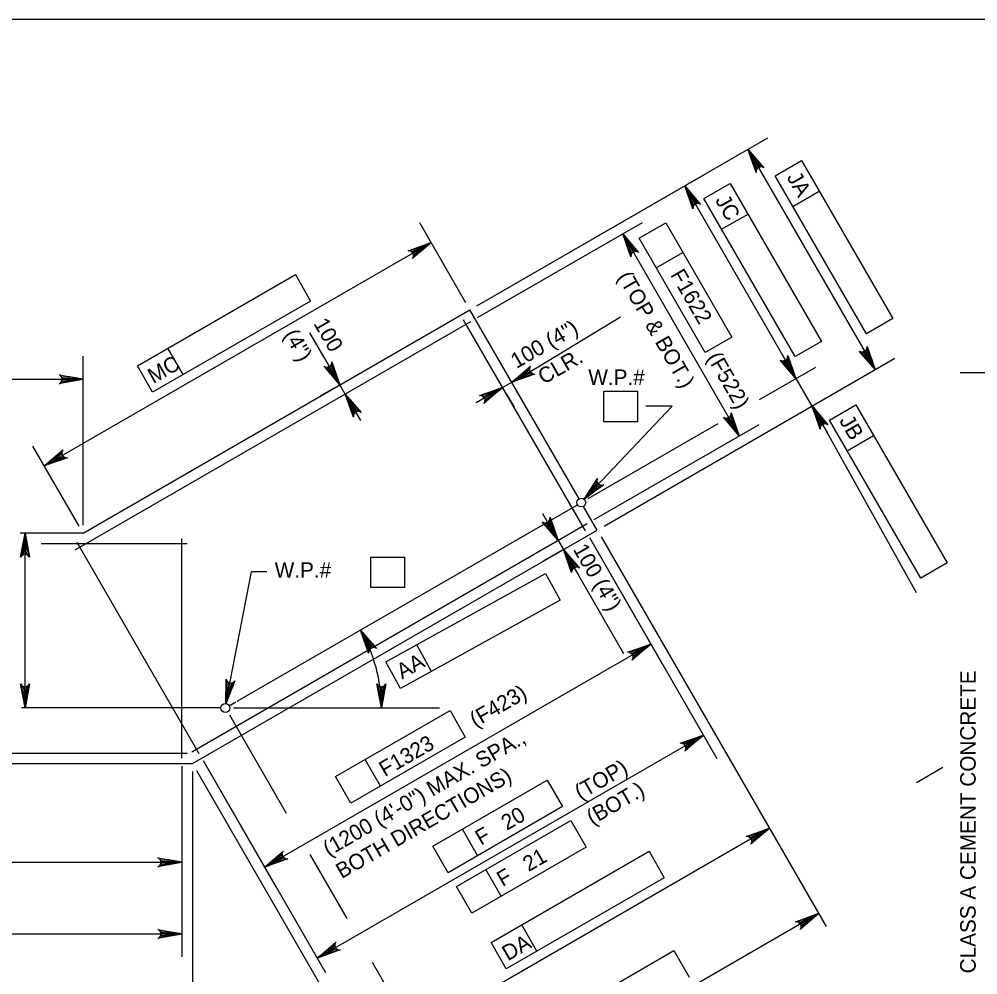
# Model space of a CAD drawing. Extents: x 634540 to 640306, y 296059 to 300275.
# Drawn here: x 639655.1 to 639840.5, y 297641.6 to 297826.5 of the extents above; entities that cross this region are included whole.
import ezdxf

# ---------------------------------------------------------------- set-up
doc = ezdxf.new("R2010")
doc.units = 0
for name, color, linetype in [('10', 7, 'Continuous'), ('2', 7, 'Continuous'), ('4', 7, 'Continuous'), ('6', 7, 'Continuous')]:
    doc.layers.add(name, color=color, linetype=linetype)

msp = doc.modelspace()

# ---------------------------------------------------------------- linework, layer by layer
at = {"layer": '10'}
for p, q in [((639667.47, 297727.03), (639742.3, 297770.24)), ((639763.41, 297733.68), (639742.3, 297770.24)), ((639697.24, 297694.5), (639763.1, 297732.52)), ((639766.91, 297727.62), (639764.26, 297732.21)), ((639688.64, 297682.43), (639766.91, 297727.62)), ((639667.47, 297727.03), (639655.32, 297727.03)), ((639695.72, 297693.62), (639697.01, 297694.37)), ((639694.14, 297693.2), (639655.55, 297693.2)), ((639468.96, 297682.43), (639688.64, 297682.43))]:
    msp.add_line(p, q, dxfattribs=at)
at = {"layer": '2'}
msp.add_line((639316.46, 297826.46), (640102.46, 297826.46), dxfattribs=at)
at = {"layer": '4'}
for p, q in [((639743.63, 297771.01), (639799.91, 297803.5)), ((639796.07, 297801.28), (639820.68, 297758.66)), ((639801.32, 297796.15), (639806.44, 297799.1)), ((639806.44, 297799.1), (639824.09, 297768.53)), ((639743.63, 297771.01), (639787.66, 297796.43)), ((639787.54, 297791.74), (639792.66, 297794.69)), ((639792.66, 297794.69), (639810.31, 297764.12)), ((639818.98, 297765.57), (639801.32, 297796.15)), ((639783.83, 297794.21), (639803.88, 297759.48)), ((639804.75, 297790.22), (639809.86, 297793.17)), ((639805.19, 297761.17), (639787.54, 297791.74)), ((639790.97, 297785.81), (639796.08, 297788.76)), ((639741.53, 297771.57), (639732.59, 297787.06)), ((639743.77, 297768.72), (639775.68, 297787.14)), ((639775.05, 297784.08), (639780.16, 297787.03)), ((639780.16, 297787.03), (639792.93, 297764.92)), ((639659.97, 297740.02), (639734.8, 297783.23)), ((639771.84, 297784.93), (639794.39, 297745.85)), ((639787.82, 297761.96), (639775.05, 297784.08)), ((639778.34, 297778.37), (639783.46, 297781.33)), ((639677.96, 297759.39), (639708.53, 297777.04)), ((639708.53, 297777.04), (639711.48, 297771.93)), ((639711.48, 297771.93), (639680.91, 297754.28)), ((639755.5, 297759.18), (639771.39, 297768.88)), ((639824.09, 297768.53), (639818.98, 297765.57)), ((639714.2, 297760.83), (639711.34, 297765.8)), ((639792.93, 297764.92), (639787.82, 297761.96)), ((639686.84, 297757.7), (639683.89, 297762.82)), ((639810.31, 297764.12), (639805.19, 297761.17)), ((639667.47, 297728.57), (639667.47, 297761.24)), ((639805.36, 297756.92), (639802.41, 297762.03)), ((639680.91, 297754.28), (639677.96, 297759.39)), ((639717.16, 297755.72), (639714.2, 297760.83)), ((639750.39, 297756.23), (639755.5, 297759.18)), ((639768.24, 297728.39), (639824.51, 297760.88)), ((639798.31, 297752.85), (639809.2, 297759.13)), ((639860.36, 297758.02), (639837.14, 297758.02)), ((639493.22, 297756.81), (639667.47, 297756.81)), ((639718.18, 297753.94), (639717.16, 297755.72)), ((639748.61, 297755.2), (639750.39, 297756.23)), ((639805.36, 297756.92), (639808.44, 297751.59)), ((639715.9, 297755), (639713.32, 297753.51)), ((639718.18, 297753.94), (639721.13, 297748.83)), ((639748.61, 297755.2), (639743.5, 297752.25)), ((639749.36, 297753.91), (639750.83, 297751.37)), ((639751.13, 297754.94), (639752.6, 297752.39)), ((639768.19, 297754.47), (639774.78, 297754.47)), ((639768.19, 297748.57), (639768.19, 297754.47)), ((639774.78, 297748.57), (639774.78, 297754.47)), ((639809.77, 297752.36), (639812.27, 297753.81)), ((639716.93, 297753.22), (639714.34, 297751.73)), ((639811.84, 297748.87), (639816.95, 297751.82)), ((639816.95, 297751.82), (639834.6, 297721.25)), ((639764.36, 297733.62), (639781.38, 297751.56)), ((639781.38, 297751.56), (639776.29, 297751.56)), ((639808.51, 297751.64), (639828.63, 297715.54)), ((639765.16, 297733.71), (639790.32, 297748.24)), ((639766.33, 297729.65), (639798.23, 297748.07)), ((639774.78, 297748.57), (639768.19, 297748.57)), ((639809.91, 297749.04), (639811.39, 297746.48)), ((639829.49, 297718.29), (639811.84, 297748.87)), ((639815.26, 297742.94), (639820.38, 297745.89)), ((639666.7, 297728.36), (639657.75, 297743.86)), ((639759.36, 297725.63), (639756.41, 297730.74)), ((639656.24, 297693.2), (639656.24, 297727.03)), ((639765.39, 297726.15), (639790.06, 297683.42)), ((639765.39, 297726.15), (639779.49, 297701.72)), ((639767.68, 297726.29), (639811.18, 297650.94)), ((639759.09, 297725.47), (639755.52, 297723.41)), ((639759.36, 297725.63), (639760.38, 297723.85)), ((639723.13, 297722.39), (639729.73, 297722.39)), ((639723.13, 297716.49), (639723.13, 297722.39)), ((639729.73, 297716.49), (639729.73, 297722.39)), ((639760.12, 297723.7), (639756.55, 297721.64)), ((639760.38, 297723.85), (639763.34, 297718.74)), ((639834.6, 297721.25), (639829.49, 297718.29)), ((639695.1, 297694.03), (639700.04, 297719.55)), ((639703, 297719.55), (639700.04, 297719.55)), ((639726.01, 297702.12), (639756.88, 297719.24)), ((639756.88, 297719.24), (639759.74, 297714.08)), ((639763.34, 297718.74), (639772, 297703.73)), ((639729.73, 297716.49), (639723.13, 297716.49)), ((639759.74, 297714.08), (639728.87, 297696.95)), ((639702.56, 297662.42), (639777.28, 297705.56)), ((639734.86, 297700.28), (639731.99, 297705.44)), ((639728.87, 297696.95), (639726.01, 297702.12)), ((639696.53, 297693.2), (639736.43, 297693.2)), ((639716.32, 297679.92), (639738.44, 297692.69)), ((639738.44, 297692.69), (639741.39, 297687.57)), ((639695.76, 297691.86), (639706.72, 297672.87)), ((639712.73, 297644.82), (639787.44, 297687.96)), ((639741.39, 297687.57), (639719.27, 297674.8)), ((639724.98, 297678.1), (639722.03, 297683.21)), ((639686.59, 297681.92), (639686.59, 297645.06)), ((639686.59, 297681.92), (639686.59, 297658.93)), ((639690.68, 297683.01), (639714.35, 297642.01)), ((639690.68, 297683.01), (639704.78, 297658.59)), ((639833.75, 297681.67), (639828.64, 297678.71)), ((639688.64, 297680.89), (639688.64, 297627.12)), ((639689.41, 297681.1), (639733.68, 297604.43)), ((639689.41, 297681.1), (639721.95, 297624.74)), ((639719.27, 297674.8), (639716.32, 297679.92)), ((639735.12, 297666.45), (639757.23, 297679.22)), ((639757.23, 297679.22), (639760.19, 297674.11)), ((639760.19, 297674.11), (639738.07, 297661.34)), ((639739.69, 297658.64), (639761.81, 297671.41)), ((639761.81, 297671.41), (639764.76, 297666.29)), ((639800.21, 297669.93), (639731.37, 297630.18)), ((639743.78, 297664.63), (639740.83, 297669.75)), ((639738.07, 297661.34), (639735.12, 297666.45)), ((639711.35, 297664.88), (639718.49, 297652.48)), ((639764.76, 297666.29), (639742.64, 297653.53)), ((639746.37, 297647.82), (639776.94, 297665.47)), ((639776.94, 297665.47), (639779.89, 297660.36)), ((639471.01, 297663.36), (639686.59, 297663.36)), ((639748.35, 297656.82), (639745.4, 297661.94)), ((639779.89, 297660.36), (639749.32, 297642.71)), ((639742.64, 297653.53), (639739.69, 297658.64)), ((639809.74, 297653.43), (639731.48, 297608.25)), ((639755.25, 297646.13), (639752.3, 297651.24)), ((639471.01, 297649.49), (639686.59, 297649.49)), ((639749.32, 297642.71), (639746.37, 297647.82)), ((639751.18, 297628.6), (639781.76, 297646.26)), ((639781.76, 297646.26), (639784.71, 297641.14)), ((639723.38, 297644.01), (639733.58, 297626.35))]:
    msp.add_line(p, q, dxfattribs=at)
for points in [[(639797.97, 297798.97), (639797.12, 297798.48), (639796.07, 297801.28)], [(639785.73, 297791.9), (639784.88, 297791.41), (639783.83, 297794.21)], [(639732, 297782.18), (639732.49, 297781.33), (639734.8, 297783.23)], [(639773.74, 297782.61), (639772.89, 297782.12), (639771.84, 297784.93)], [(639819.63, 297761.46), (639818.78, 297760.97), (639820.68, 297758.66)], [(639804.31, 297759.72), (639803.46, 297759.23), (639805.36, 297756.92)], [(639664.51, 297757.3), (639664.51, 297756.32), (639667.47, 297756.81)], [(639716.1, 297758.52), (639715.25, 297758.03), (639717.16, 297755.72)], [(639752.7, 297758.13), (639753.19, 297757.28), (639750.39, 297756.23)], [(639720.08, 297751.63), (639719.23, 297751.14), (639718.18, 297753.94)], [(639745.81, 297754.15), (639746.3, 297753.3), (639748.61, 297755.2)], [(639810.34, 297749.28), (639809.49, 297748.79), (639808.44, 297751.59)], [(639793.34, 297748.66), (639792.49, 297748.17), (639794.39, 297745.85)], [(639662.28, 297741.93), (639662.77, 297741.07), (639659.97, 297740.02)], [(639766.75, 297735.41), (639766.04, 297736.09), (639764.36, 297733.61)], [(639758.31, 297728.43), (639757.46, 297727.94), (639759.36, 297725.63)], [(639656.73, 297724.08), (639655.75, 297724.08), (639656.24, 297727.03)], [(639762.29, 297721.54), (639761.44, 297721.05), (639760.38, 297723.85)], [(639774.47, 297704.51), (639774.96, 297703.65), (639777.28, 297705.56)], [(639656.73, 297696.15), (639655.75, 297696.15), (639656.24, 297693.2)], [(639696.15, 297696.84), (639695.18, 297697.03), (639695.1, 297694.04)], [(639784.63, 297686.9), (639785.13, 297686.05), (639787.44, 297687.95)], [(639797.41, 297668.88), (639797.9, 297668.02), (639800.21, 297669.93)], [(639683.64, 297663.86), (639683.64, 297662.87), (639686.59, 297663.36)], [(639704.88, 297664.33), (639705.37, 297663.47), (639702.56, 297662.42)], [(639806.94, 297652.38), (639807.43, 297651.53), (639809.74, 297653.43)], [(639683.64, 297649.98), (639683.64, 297649), (639686.59, 297649.49)], [(639715.04, 297646.72), (639715.53, 297645.87), (639712.73, 297644.82)]]:
    msp.add_lwpolyline(points, close=True, dxfattribs=at)
for points in [[(639796.07, 297801.28), (639799.16, 297797.68), (639798.76, 297797.87), (639798.4, 297797.87), (639798.1, 297797.76), (639797.86, 297797.56), (639797.68, 297797.24), (639797.64, 297796.81), (639796.07, 297801.28), (639797.68, 297797.24), (639797.86, 297797.56), (639796.07, 297801.28), (639798.1, 297797.76), (639798.4, 297797.87), (639796.07, 297801.28), (639798.76, 297797.87)], [(639783.83, 297794.21), (639786.92, 297790.61), (639786.52, 297790.8), (639786.16, 297790.8), (639785.86, 297790.69), (639785.62, 297790.49), (639785.44, 297790.18), (639785.4, 297789.74), (639783.83, 297794.21), (639785.44, 297790.18), (639785.62, 297790.49), (639783.83, 297794.21), (639785.86, 297790.69), (639786.16, 297790.8), (639783.83, 297794.21), (639786.52, 297790.8)], [(639734.8, 297783.23), (639731.2, 297780.14), (639731.39, 297780.54), (639731.39, 297780.9), (639731.28, 297781.2), (639731.08, 297781.44), (639730.76, 297781.62), (639730.33, 297781.66), (639734.8, 297783.23), (639730.76, 297781.62), (639731.08, 297781.44), (639734.8, 297783.23), (639731.28, 297781.2), (639731.39, 297780.9), (639734.8, 297783.23), (639731.39, 297780.54)], [(639771.84, 297784.93), (639774.93, 297781.33), (639774.53, 297781.51), (639774.17, 297781.52), (639773.87, 297781.41), (639773.63, 297781.2), (639773.45, 297780.89), (639773.41, 297780.45), (639771.84, 297784.93), (639773.45, 297780.89), (639773.63, 297781.2), (639771.84, 297784.93), (639773.87, 297781.41), (639774.17, 297781.52), (639771.84, 297784.93), (639774.53, 297781.51)], [(639820.68, 297758.66), (639817.59, 297762.26), (639817.99, 297762.07), (639818.35, 297762.07), (639818.65, 297762.18), (639818.89, 297762.38), (639819.07, 297762.7), (639819.1, 297763.13), (639820.68, 297758.66), (639819.07, 297762.7), (639818.89, 297762.38), (639820.68, 297758.66), (639818.65, 297762.18), (639818.35, 297762.07), (639820.68, 297758.66), (639817.99, 297762.07)], [(639805.36, 297756.92), (639802.27, 297760.52), (639802.67, 297760.33), (639803.03, 297760.33), (639803.33, 297760.44), (639803.57, 297760.64), (639803.75, 297760.96), (639803.78, 297761.39), (639805.36, 297756.92), (639803.75, 297760.96), (639803.57, 297760.64), (639805.36, 297756.92), (639803.33, 297760.44), (639803.03, 297760.33), (639805.36, 297756.92), (639802.67, 297760.33)], [(639717.16, 297755.72), (639714.07, 297759.32), (639714.46, 297759.13), (639714.83, 297759.13), (639715.12, 297759.24), (639715.37, 297759.44), (639715.55, 297759.76), (639715.58, 297760.19), (639717.16, 297755.72), (639715.55, 297759.76), (639715.37, 297759.44), (639717.16, 297755.72), (639715.12, 297759.24), (639714.83, 297759.13), (639717.16, 297755.72), (639714.46, 297759.13)], [(639750.39, 297756.23), (639753.99, 297759.31), (639753.8, 297758.92), (639753.8, 297758.56), (639753.91, 297758.26), (639754.11, 297758.02), (639754.43, 297757.84), (639754.86, 297757.8), (639750.39, 297756.23), (639754.43, 297757.84), (639754.11, 297758.02), (639750.39, 297756.23), (639753.91, 297758.26), (639753.8, 297758.56), (639750.39, 297756.23), (639753.8, 297758.92)], [(639667.47, 297756.81), (639662.81, 297755.94), (639663.16, 297756.18), (639663.35, 297756.5), (639663.4, 297756.81), (639663.35, 297757.12), (639663.16, 297757.43), (639662.81, 297757.68), (639667.47, 297756.81), (639663.16, 297757.43), (639663.35, 297757.12), (639667.47, 297756.81), (639663.4, 297756.81), (639663.35, 297756.5), (639667.47, 297756.81), (639663.16, 297756.18)], [(639718.18, 297753.94), (639721.27, 297750.34), (639720.87, 297750.53), (639720.51, 297750.54), (639720.21, 297750.43), (639719.97, 297750.22), (639719.79, 297749.91), (639719.75, 297749.47), (639718.18, 297753.94), (639719.79, 297749.91), (639719.97, 297750.22), (639718.18, 297753.94), (639720.21, 297750.43), (639720.51, 297750.54), (639718.18, 297753.94), (639720.87, 297750.53)], [(639748.61, 297755.2), (639745.01, 297752.11), (639745.2, 297752.51), (639745.21, 297752.87), (639745.09, 297753.17), (639744.89, 297753.41), (639744.58, 297753.59), (639744.14, 297753.63), (639748.61, 297755.2), (639744.58, 297753.59), (639744.89, 297753.41), (639748.61, 297755.2), (639745.09, 297753.17), (639745.21, 297752.87), (639748.61, 297755.2), (639745.2, 297752.51)], [(639794.39, 297745.85), (639791.31, 297749.45), (639791.7, 297749.27), (639792.07, 297749.26), (639792.36, 297749.37), (639792.61, 297749.58), (639792.79, 297749.89), (639792.82, 297750.33), (639794.39, 297745.85), (639792.79, 297749.89), (639792.61, 297749.58), (639794.39, 297745.85), (639792.36, 297749.37), (639792.07, 297749.26), (639794.39, 297745.85), (639791.7, 297749.27)], [(639808.51, 297751.64), (639811.54, 297747.99), (639811.15, 297748.18), (639810.79, 297748.19), (639810.49, 297748.09), (639810.24, 297747.89), (639810.06, 297747.58), (639810.02, 297747.14), (639808.51, 297751.64), (639810.06, 297747.58), (639810.24, 297747.89), (639808.51, 297751.64), (639810.49, 297748.09), (639810.79, 297748.19), (639808.51, 297751.64), (639811.15, 297748.18)], [(639659.97, 297740.02), (639663.57, 297743.11), (639663.38, 297742.71), (639663.37, 297742.35), (639663.48, 297742.05), (639663.69, 297741.81), (639664, 297741.63), (639664.44, 297741.6), (639659.97, 297740.02), (639664, 297741.63), (639663.69, 297741.81), (639659.97, 297740.02), (639663.48, 297742.05), (639663.37, 297742.35), (639659.97, 297740.02), (639663.38, 297742.71)], [(639764.36, 297733.62), (639766.94, 297737.6), (639766.87, 297737.17), (639766.97, 297736.82), (639767.16, 297736.56), (639767.42, 297736.39), (639767.78, 297736.31), (639768.21, 297736.4), (639764.36, 297733.62), (639767.78, 297736.31), (639767.42, 297736.39), (639764.36, 297733.62), (639767.16, 297736.56), (639766.97, 297736.82), (639764.36, 297733.62), (639766.87, 297737.17)], [(639759.36, 297725.63), (639756.27, 297729.22), (639756.67, 297729.04), (639757.03, 297729.04), (639757.33, 297729.15), (639757.57, 297729.35), (639757.75, 297729.66), (639757.78, 297730.1), (639759.36, 297725.63), (639757.75, 297729.66), (639757.57, 297729.35), (639759.36, 297725.63), (639757.33, 297729.15), (639757.03, 297729.04), (639759.36, 297725.63), (639756.67, 297729.04)], [(639656.24, 297727.03), (639657.11, 297722.37), (639656.86, 297722.73), (639656.55, 297722.92), (639656.24, 297722.97), (639655.93, 297722.92), (639655.61, 297722.73), (639655.37, 297722.37), (639656.24, 297727.03), (639655.61, 297722.73), (639655.93, 297722.92), (639656.24, 297727.03), (639656.24, 297722.97), (639656.55, 297722.92), (639656.24, 297727.03), (639656.86, 297722.73)], [(639760.38, 297723.85), (639763.47, 297720.25), (639763.08, 297720.44), (639762.71, 297720.44), (639762.42, 297720.33), (639762.17, 297720.13), (639761.99, 297719.81), (639761.96, 297719.38), (639760.38, 297723.85), (639761.99, 297719.81), (639762.17, 297720.13), (639760.38, 297723.85), (639762.42, 297720.33), (639762.71, 297720.44), (639760.38, 297723.85), (639763.08, 297720.44)], [(639721.12, 297708.28), (639724.21, 297704.68), (639723.81, 297704.87), (639723.45, 297704.88), (639723.15, 297704.77), (639722.91, 297704.56), (639722.73, 297704.25), (639722.69, 297703.81), (639721.12, 297708.28), (639722.73, 297704.25), (639722.91, 297704.56), (639721.12, 297708.28), (639723.15, 297704.77), (639723.45, 297704.88), (639721.12, 297708.28), (639723.81, 297704.87)], [(639777.28, 297705.56), (639773.68, 297702.47), (639773.86, 297702.87), (639773.87, 297703.23), (639773.76, 297703.53), (639773.55, 297703.77), (639773.24, 297703.95), (639772.8, 297703.98), (639777.28, 297705.56), (639773.24, 297703.95), (639773.55, 297703.77), (639777.28, 297705.56), (639773.76, 297703.53), (639773.87, 297703.23), (639777.28, 297705.56), (639773.86, 297702.87)], [(639695.1, 297694.03), (639695.13, 297698.77), (639695.31, 297698.37), (639695.58, 297698.13), (639695.88, 297698.02), (639696.19, 297698.01), (639696.53, 297698.14), (639696.85, 297698.44), (639695.1, 297694.03), (639696.53, 297698.14), (639696.19, 297698.01), (639695.1, 297694.03), (639695.88, 297698.02), (639695.58, 297698.13), (639695.1, 297694.03), (639695.31, 297698.37)], [(639656.24, 297693.2), (639655.37, 297697.86), (639655.61, 297697.5), (639655.93, 297697.31), (639656.24, 297697.26), (639656.55, 297697.31), (639656.86, 297697.5), (639657.11, 297697.86), (639656.24, 297693.2), (639656.86, 297697.5), (639656.55, 297697.31), (639656.24, 297693.2), (639656.24, 297697.26), (639655.93, 297697.31), (639656.24, 297693.2), (639655.61, 297697.5)], [(639725.16, 297693.2), (639724.29, 297697.86), (639724.54, 297697.5), (639724.85, 297697.31), (639725.16, 297697.26), (639725.47, 297697.31), (639725.79, 297697.5), (639726.04, 297697.86), (639725.16, 297693.2), (639725.79, 297697.5), (639725.47, 297697.31), (639725.16, 297693.2), (639725.16, 297697.26), (639724.85, 297697.31), (639725.16, 297693.2), (639724.54, 297697.5)], [(639787.44, 297687.96), (639783.84, 297684.87), (639784.03, 297685.26), (639784.03, 297685.63), (639783.92, 297685.92), (639783.72, 297686.17), (639783.4, 297686.35), (639782.97, 297686.38), (639787.44, 297687.96), (639783.4, 297686.35), (639783.72, 297686.17), (639787.44, 297687.96), (639783.92, 297685.92), (639784.03, 297685.63), (639787.44, 297687.96), (639784.03, 297685.26)], [(639800.21, 297669.93), (639796.61, 297666.84), (639796.8, 297667.24), (639796.81, 297667.6), (639796.69, 297667.9), (639796.49, 297668.14), (639796.18, 297668.32), (639795.74, 297668.36), (639800.21, 297669.93), (639796.18, 297668.32), (639796.49, 297668.14), (639800.21, 297669.93), (639796.69, 297667.9), (639796.81, 297667.6), (639800.21, 297669.93), (639796.8, 297667.24)], [(639702.56, 297662.42), (639706.16, 297665.51), (639705.98, 297665.12), (639705.97, 297664.75), (639706.08, 297664.46), (639706.28, 297664.21), (639706.6, 297664.03), (639707.04, 297664), (639702.56, 297662.42), (639706.6, 297664.03), (639706.28, 297664.21), (639702.56, 297662.42), (639706.08, 297664.46), (639705.97, 297664.75), (639702.56, 297662.42), (639705.98, 297665.12)], [(639686.59, 297663.36), (639681.93, 297662.49), (639682.29, 297662.74), (639682.48, 297663.05), (639682.53, 297663.36), (639682.48, 297663.68), (639682.29, 297663.99), (639681.93, 297664.24), (639686.59, 297663.36), (639682.29, 297663.99), (639682.48, 297663.68), (639686.59, 297663.36), (639682.53, 297663.36), (639682.48, 297663.05), (639686.59, 297663.36), (639682.29, 297662.74)], [(639809.74, 297653.43), (639806.14, 297650.34), (639806.33, 297650.74), (639806.33, 297651.1), (639806.22, 297651.4), (639806.02, 297651.64), (639805.7, 297651.82), (639805.27, 297651.86), (639809.74, 297653.43), (639805.7, 297651.82), (639806.02, 297651.64), (639809.74, 297653.43), (639806.22, 297651.4), (639806.33, 297651.1), (639809.74, 297653.43), (639806.33, 297650.74)], [(639686.59, 297649.49), (639681.93, 297648.62), (639682.29, 297648.86), (639682.48, 297649.18), (639682.53, 297649.49), (639682.48, 297649.8), (639682.29, 297650.11), (639681.93, 297650.36), (639686.59, 297649.49), (639682.29, 297650.11), (639682.48, 297649.8), (639686.59, 297649.49), (639682.53, 297649.49), (639682.48, 297649.18), (639686.59, 297649.49), (639682.29, 297648.86)], [(639712.73, 297644.82), (639716.33, 297647.91), (639716.14, 297647.51), (639716.14, 297647.15), (639716.25, 297646.85), (639716.45, 297646.61), (639716.76, 297646.43), (639717.2, 297646.39), (639712.73, 297644.82), (639716.76, 297646.43), (639716.45, 297646.61), (639712.73, 297644.82), (639716.25, 297646.85), (639716.14, 297647.15), (639712.73, 297644.82), (639716.14, 297647.51)]]:
    msp.add_lwpolyline(points, dxfattribs=at)
for centre in [(639763.83, 297732.94), (639694.99, 297693.2)]:
    msp.add_circle(centre, 0.85, dxfattribs=at)
msp.add_arc((639694.99, 297693.2), 30.17, 0.0017, 29.9999, dxfattribs=at)
at = {"layer": '6'}
for p, q in [((639665.95, 297723.79), (639742.44, 297767.95)), ((639764.62, 297727.48), (639741.04, 297768.32)), ((639688.51, 297684.72), (639764.99, 297728.88)), ((639686.59, 297683.46), (639686.59, 297726.01)), ((639687.62, 297724.98), (639659.35, 297724.98)), ((639689.91, 297684.35), (639666.33, 297725.19)), ((639469.99, 297684.48), (639687.62, 297684.48))]:
    msp.add_line(p, q, dxfattribs=at)

# ---------------------------------------------------------------- texts
at = {"layer": '4'}
for s, height, rotation, p in [('JA', 3, 300, (639803.49, 297795.86)), ('JC', 3, 300, (639789.65, 297791.42)), ('F1622', 3, 300, (639780.99, 297777.02)), ('(TOP & BOT.)', 3.0001, 300, (639770.75, 297776.59)), ('100', 3, 300, (639711.97, 297767.57)), ('100 (4")', 3, 30, (639751.29, 297758.77)), ('(4")', 3, 300, (639706.2, 297765.41)), ('MC', 3, 30, (639681.07, 297755.84)), ('CLR.', 3, 30, (639756.55, 297755.71)), ('(F522)', 3, 300, (639788.04, 297760.98)), ('JB', 3, 300, (639813.65, 297748.8)), ('100 (4")', 3, 300, (639762.15, 297723.91)), ('AA', 3, 29.0163, (639729.15, 297698.71)), ('CLASS A CEMENT CONCRETE', 3.0001, 90, (639840.12, 297641.86)), ('(F423)', 3, 30, (639743.37, 297689.37)), ('(1200 (4\'-0") MAX. SPA.,', 3.0001, 30, (639714.97, 297664.42)), ('F1323', 3, 30, (639725.82, 297679.81)), ('BOTH DIRECTIONS)', 3.0001, 30, (639717.47, 297660.09)), ('(TOP)', 3, 30, (639763.66, 297675.33)), ('(BOT.)', 3, 30, (639765.96, 297670.48)), ('F   20', 3, 30, (639744.42, 297666.54)), ('F   21', 3, 30, (639748.6, 297658.54)), ('DA', 3, 30, (639749.62, 297644.18))]:
    msp.add_text(s, height=height, rotation=rotation, dxfattribs=at).set_placement(p)
for p in [(639765.19, 297755.69), (639704.53, 297718.39)]:
    msp.add_text('W.P.#', height=3, dxfattribs=at).set_placement(p)

doc.saveas('drawing.dxf')
